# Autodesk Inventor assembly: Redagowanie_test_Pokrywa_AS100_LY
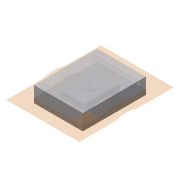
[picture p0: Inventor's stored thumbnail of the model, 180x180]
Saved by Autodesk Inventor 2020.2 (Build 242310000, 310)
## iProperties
Created: 2015-11
Part Number: Redagowanie_test_Pokrywa_AS100_LY
Document SubType Name: Assembly
Designer: F.Stasiak
Catalog Web Link: www.expertbooks.pl
Manager: www.cadconsulting.pl
Company: Fabian Stasiak CAD Consulting
Author: F.Stasiak
Subject: Zbiór ćwiczeń. Autodesk Inventor 2020. Kurs Professional
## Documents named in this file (2)
- C:\2020_Kurs_Professional\R6 Formy\Redagowanie\Redagowanie_test_Pokrywa_AS100_LY.iam
- C:\2020_Kurs_Professional\R6 Formy\Redagowanie\Redagowanie_test_Pokrywa_AS100_PZ.iam
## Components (1 placed, 1 different names)
1. Redagowanie_test_Pokrywa_AS100_PZ:1 [sub-assembly] — Równoległy:1, Równoległy:2, Równoległy:3
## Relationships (3: Flush 3)
- Równoległy:1 [Flush]: Redagowanie_test_Pokrywa_AS100_PZ:1
- Równoległy:2 [Flush]: Redagowanie_test_Pokrywa_AS100_PZ:1
- Równoległy:3 [Flush]: Redagowanie_test_Pokrywa_AS100_PZ:1
